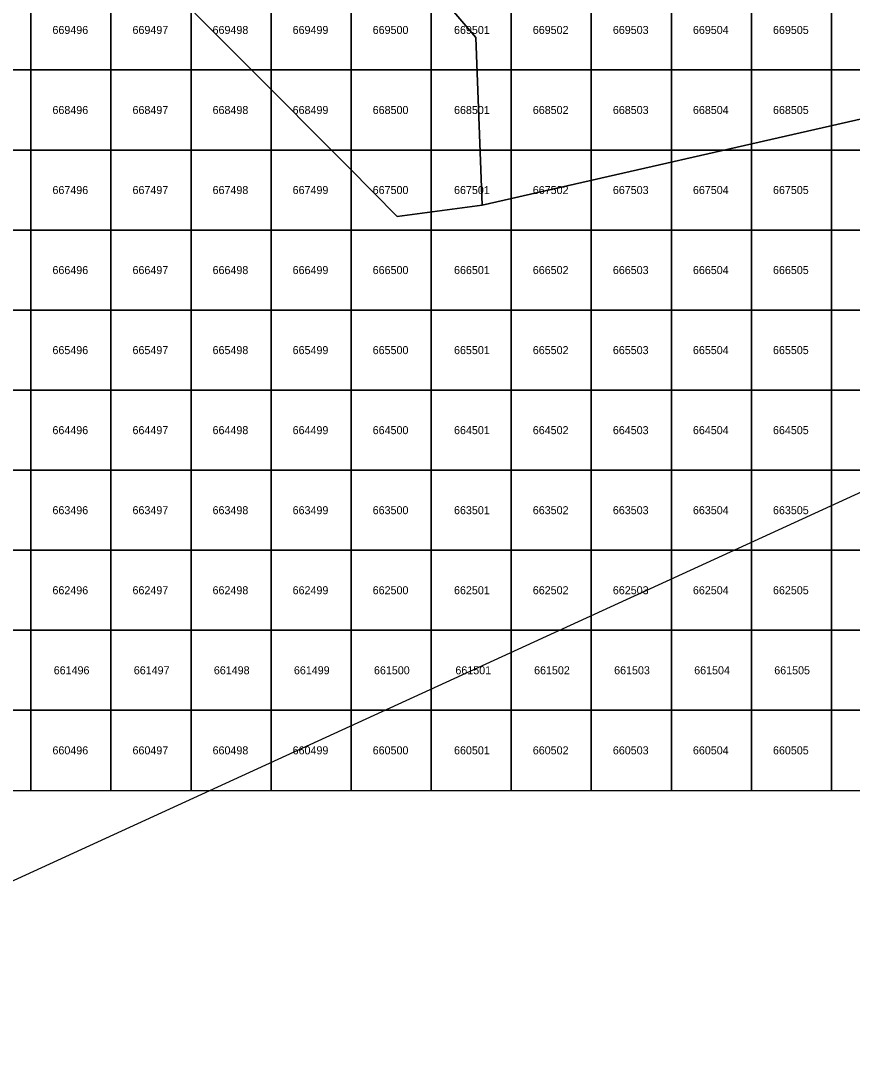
# Model space of a CAD drawing. Extents: x 25485000 to 25520000, y 6656775 to 6690000.
# Drawn here: x 25495870 to 25506262, y 6656775 to 6669617 of the extents above; entities that cross this region are included whole.
import ezdxf

# ---------------------------------------------------------------- set-up
doc = ezdxf.new("R2010")
doc.units = 0
doc.layers.add('Level 63', color=7, linetype='Continuous')

msp = doc.modelspace()

# ---------------------------------------------------------------- linework, layer by layer
at = {"layer": 'Level 63'}
for points in [[(25497357, 6670410), (25497407, 6670360), (25499970, 6667780), (25500576, 6667171), (25501638, 6667311), (25501556, 6669405), (25501232, 6669785), (25501233, 6670418), (25501234, 6671696), (25501017, 6671717), (25500288, 6671786), (25497878, 6670961), (25497622, 6671122), (25497572, 6671153), (25497412, 6670926)], [(25495000, 6669000), (25496000, 6669000), (25496000, 6670000), (25495000, 6670000)], [(25496000, 6669000), (25497000, 6669000), (25497000, 6670000), (25496000, 6670000)], [(25497000, 6669000), (25498000, 6669000), (25498000, 6670000), (25497000, 6670000)], [(25498000, 6669000), (25499000, 6669000), (25499000, 6670000), (25498000, 6670000)], [(25499000, 6669000), (25500000, 6669000), (25500000, 6670000), (25499000, 6670000)], [(25500000, 6669000), (25501000, 6669000), (25501000, 6670000), (25500000, 6670000)], [(25501000, 6669000), (25502000, 6669000), (25502000, 6670000), (25501000, 6670000)], [(25502000, 6669000), (25503000, 6669000), (25503000, 6670000), (25502000, 6670000)], [(25503000, 6669000), (25504000, 6669000), (25504000, 6670000), (25503000, 6670000)], [(25504000, 6669000), (25505000, 6669000), (25505000, 6670000), (25504000, 6670000)], [(25505000, 6669000), (25506000, 6669000), (25506000, 6670000), (25505000, 6670000)], [(25506000, 6669000), (25507000, 6669000), (25507000, 6670000), (25506000, 6670000)], [(25495000, 6668000), (25496000, 6668000), (25496000, 6669000), (25495000, 6669000)], [(25496000, 6668000), (25497000, 6668000), (25497000, 6669000), (25496000, 6669000)], [(25497000, 6668000), (25498000, 6668000), (25498000, 6669000), (25497000, 6669000)], [(25498000, 6668000), (25499000, 6668000), (25499000, 6669000), (25498000, 6669000)], [(25499000, 6668000), (25500000, 6668000), (25500000, 6669000), (25499000, 6669000)], [(25500000, 6668000), (25501000, 6668000), (25501000, 6669000), (25500000, 6669000)], [(25501000, 6668000), (25502000, 6668000), (25502000, 6669000), (25501000, 6669000)], [(25502000, 6668000), (25503000, 6668000), (25503000, 6669000), (25502000, 6669000)], [(25503000, 6668000), (25504000, 6668000), (25504000, 6669000), (25503000, 6669000)], [(25504000, 6668000), (25505000, 6668000), (25505000, 6669000), (25504000, 6669000)], [(25505000, 6668000), (25506000, 6668000), (25506000, 6669000), (25505000, 6669000)], [(25506000, 6668000), (25507000, 6668000), (25507000, 6669000), (25506000, 6669000)], [(25495000, 6667000), (25496000, 6667000), (25496000, 6668000), (25495000, 6668000)], [(25496000, 6667000), (25497000, 6667000), (25497000, 6668000), (25496000, 6668000)], [(25497000, 6667000), (25498000, 6667000), (25498000, 6668000), (25497000, 6668000)], [(25498000, 6667000), (25499000, 6667000), (25499000, 6668000), (25498000, 6668000)], [(25499000, 6667000), (25500000, 6667000), (25500000, 6668000), (25499000, 6668000)], [(25500000, 6667000), (25501000, 6667000), (25501000, 6668000), (25500000, 6668000)], [(25501000, 6667000), (25502000, 6667000), (25502000, 6668000), (25501000, 6668000)], [(25502000, 6667000), (25503000, 6667000), (25503000, 6668000), (25502000, 6668000)], [(25503000, 6667000), (25504000, 6667000), (25504000, 6668000), (25503000, 6668000)], [(25504000, 6667000), (25505000, 6667000), (25505000, 6668000), (25504000, 6668000)], [(25505000, 6667000), (25506000, 6667000), (25506000, 6668000), (25505000, 6668000)], [(25506000, 6667000), (25507000, 6667000), (25507000, 6668000), (25506000, 6668000)], [(25495000, 6666000), (25496000, 6666000), (25496000, 6667000), (25495000, 6667000)], [(25496000, 6666000), (25497000, 6666000), (25497000, 6667000), (25496000, 6667000)], [(25497000, 6666000), (25498000, 6666000), (25498000, 6667000), (25497000, 6667000)], [(25498000, 6666000), (25499000, 6666000), (25499000, 6667000), (25498000, 6667000)], [(25499000, 6666000), (25500000, 6666000), (25500000, 6667000), (25499000, 6667000)], [(25500000, 6666000), (25501000, 6666000), (25501000, 6667000), (25500000, 6667000)], [(25501000, 6666000), (25502000, 6666000), (25502000, 6667000), (25501000, 6667000)], [(25502000, 6666000), (25503000, 6666000), (25503000, 6667000), (25502000, 6667000)], [(25503000, 6666000), (25504000, 6666000), (25504000, 6667000), (25503000, 6667000)], [(25504000, 6666000), (25505000, 6666000), (25505000, 6667000), (25504000, 6667000)], [(25505000, 6666000), (25506000, 6666000), (25506000, 6667000), (25505000, 6667000)], [(25506000, 6666000), (25507000, 6666000), (25507000, 6667000), (25506000, 6667000)], [(25495000, 6665000), (25496000, 6665000), (25496000, 6666000), (25495000, 6666000)], [(25496000, 6665000), (25497000, 6665000), (25497000, 6666000), (25496000, 6666000)], [(25497000, 6665000), (25498000, 6665000), (25498000, 6666000), (25497000, 6666000)], [(25498000, 6665000), (25499000, 6665000), (25499000, 6666000), (25498000, 6666000)], [(25499000, 6665000), (25500000, 6665000), (25500000, 6666000), (25499000, 6666000)], [(25500000, 6665000), (25501000, 6665000), (25501000, 6666000), (25500000, 6666000)], [(25501000, 6665000), (25502000, 6665000), (25502000, 6666000), (25501000, 6666000)], [(25502000, 6665000), (25503000, 6665000), (25503000, 6666000), (25502000, 6666000)], [(25503000, 6665000), (25504000, 6665000), (25504000, 6666000), (25503000, 6666000)], [(25504000, 6665000), (25505000, 6665000), (25505000, 6666000), (25504000, 6666000)], [(25505000, 6665000), (25506000, 6665000), (25506000, 6666000), (25505000, 6666000)], [(25506000, 6665000), (25507000, 6665000), (25507000, 6666000), (25506000, 6666000)], [(25495000, 6664000), (25496000, 6664000), (25496000, 6665000), (25495000, 6665000)], [(25496000, 6664000), (25497000, 6664000), (25497000, 6665000), (25496000, 6665000)], [(25497000, 6664000), (25498000, 6664000), (25498000, 6665000), (25497000, 6665000)], [(25498000, 6664000), (25499000, 6664000), (25499000, 6665000), (25498000, 6665000)], [(25499000, 6664000), (25500000, 6664000), (25500000, 6665000), (25499000, 6665000)], [(25500000, 6664000), (25501000, 6664000), (25501000, 6665000), (25500000, 6665000)], [(25501000, 6664000), (25502000, 6664000), (25502000, 6665000), (25501000, 6665000)], [(25502000, 6664000), (25503000, 6664000), (25503000, 6665000), (25502000, 6665000)], [(25503000, 6664000), (25504000, 6664000), (25504000, 6665000), (25503000, 6665000)], [(25504000, 6664000), (25505000, 6664000), (25505000, 6665000), (25504000, 6665000)], [(25505000, 6664000), (25506000, 6664000), (25506000, 6665000), (25505000, 6665000)], [(25506000, 6664000), (25507000, 6664000), (25507000, 6665000), (25506000, 6665000)], [(25495000, 6663000), (25496000, 6663000), (25496000, 6664000), (25495000, 6664000)], [(25496000, 6663000), (25497000, 6663000), (25497000, 6664000), (25496000, 6664000)], [(25497000, 6663000), (25498000, 6663000), (25498000, 6664000), (25497000, 6664000)], [(25498000, 6663000), (25499000, 6663000), (25499000, 6664000), (25498000, 6664000)], [(25499000, 6663000), (25500000, 6663000), (25500000, 6664000), (25499000, 6664000)], [(25500000, 6663000), (25501000, 6663000), (25501000, 6664000), (25500000, 6664000)], [(25501000, 6663000), (25502000, 6663000), (25502000, 6664000), (25501000, 6664000)], [(25502000, 6663000), (25503000, 6663000), (25503000, 6664000), (25502000, 6664000)], [(25503000, 6663000), (25504000, 6663000), (25504000, 6664000), (25503000, 6664000)], [(25504000, 6663000), (25505000, 6663000), (25505000, 6664000), (25504000, 6664000)], [(25505000, 6663000), (25506000, 6663000), (25506000, 6664000), (25505000, 6664000)], [(25506000, 6663000), (25507000, 6663000), (25507000, 6664000), (25506000, 6664000)], [(25495000, 6662000), (25496000, 6662000), (25496000, 6663000), (25495000, 6663000)], [(25496000, 6662000), (25497000, 6662000), (25497000, 6663000), (25496000, 6663000)], [(25497000, 6662000), (25498000, 6662000), (25498000, 6663000), (25497000, 6663000)], [(25498000, 6662000), (25499000, 6662000), (25499000, 6663000), (25498000, 6663000)], [(25499000, 6662000), (25500000, 6662000), (25500000, 6663000), (25499000, 6663000)], [(25500000, 6662000), (25501000, 6662000), (25501000, 6663000), (25500000, 6663000)], [(25501000, 6662000), (25502000, 6662000), (25502000, 6663000), (25501000, 6663000)], [(25502000, 6662000), (25503000, 6662000), (25503000, 6663000), (25502000, 6663000)], [(25503000, 6662000), (25504000, 6662000), (25504000, 6663000), (25503000, 6663000)], [(25504000, 6662000), (25505000, 6662000), (25505000, 6663000), (25504000, 6663000)], [(25505000, 6662000), (25506000, 6662000), (25506000, 6663000), (25505000, 6663000)], [(25506000, 6662000), (25507000, 6662000), (25507000, 6663000), (25506000, 6663000)], [(25495000, 6661000), (25496000, 6661000), (25496000, 6662000), (25495000, 6662000)], [(25496000, 6661000), (25497000, 6661000), (25497000, 6662000), (25496000, 6662000)], [(25497000, 6661000), (25498000, 6661000), (25498000, 6662000), (25497000, 6662000)], [(25498000, 6661000), (25499000, 6661000), (25499000, 6662000), (25498000, 6662000)], [(25499000, 6661000), (25500000, 6661000), (25500000, 6662000), (25499000, 6662000)], [(25500000, 6661000), (25501000, 6661000), (25501000, 6662000), (25500000, 6662000)], [(25501000, 6661000), (25502000, 6661000), (25502000, 6662000), (25501000, 6662000)], [(25502000, 6661000), (25503000, 6661000), (25503000, 6662000), (25502000, 6662000)], [(25503000, 6661000), (25504000, 6661000), (25504000, 6662000), (25503000, 6662000)], [(25504000, 6661000), (25505000, 6661000), (25505000, 6662000), (25504000, 6662000)], [(25505000, 6661000), (25506000, 6661000), (25506000, 6662000), (25505000, 6662000)], [(25506000, 6661000), (25507000, 6661000), (25507000, 6662000), (25506000, 6662000)], [(25495000, 6660000), (25496000, 6660000), (25496000, 6661000), (25495000, 6661000)], [(25496000, 6660000), (25497000, 6660000), (25497000, 6661000), (25496000, 6661000)], [(25497000, 6660000), (25498000, 6660000), (25498000, 6661000), (25497000, 6661000)], [(25498000, 6660000), (25499000, 6660000), (25499000, 6661000), (25498000, 6661000)], [(25499000, 6660000), (25500000, 6660000), (25500000, 6661000), (25499000, 6661000)], [(25500000, 6660000), (25501000, 6660000), (25501000, 6661000), (25500000, 6661000)], [(25501000, 6660000), (25502000, 6660000), (25502000, 6661000), (25501000, 6661000)], [(25502000, 6660000), (25503000, 6660000), (25503000, 6661000), (25502000, 6661000)], [(25503000, 6660000), (25504000, 6660000), (25504000, 6661000), (25503000, 6661000)], [(25504000, 6660000), (25505000, 6660000), (25505000, 6661000), (25504000, 6661000)], [(25505000, 6660000), (25506000, 6660000), (25506000, 6661000), (25505000, 6661000)], [(25506000, 6660000), (25507000, 6660000), (25507000, 6661000), (25506000, 6661000)]]:
    msp.add_lwpolyline(points, close=True, dxfattribs=at)
for points in [[(25506580, 6668434), (25501638, 6667311), (25500576, 6667171), (25499970, 6667780), (25497407, 6670360), (25497357, 6670410), (25496638, 6670410), (25496588, 6670411), (25496587, 6669968), (25495369, 6669969), (25494290, 6669969), (25494289, 6669645), (25492634, 6669823), (25491001, 6669998), (25490933, 6669294), (25490867, 6668614), (25487917, 6665230), (25489109, 6662564), (25491530, 6657153), (25491699, 6656775), (25493980, 6658048), (25507391, 6664195)], [(25501232, 6669785), (25501556, 6669405), (25501638, 6667311), (25506580, 6668434)]]:
    msp.add_lwpolyline(points, dxfattribs=at)

# ---------------------------------------------------------------- texts
for s, p in [('669496', (25496269, 6669450)), ('669497', (25497269, 6669450)), ('669498', (25498269, 6669450)), ('669499', (25499269, 6669450)), ('669500', (25500269, 6669450)), ('669501', (25501285, 6669450)), ('669502', (25502269, 6669450)), ('669503', (25503269, 6669450)), ('669504', (25504269, 6669450)), ('669505', (25505269, 6669450)), ('668496', (25496269, 6668450)), ('668497', (25497269, 6668450)), ('668498', (25498269, 6668450)), ('668499', (25499269, 6668450)), ('668500', (25500269, 6668450)), ('668501', (25501285, 6668450)), ('668502', (25502269, 6668450)), ('668503', (25503269, 6668450)), ('668504', (25504269, 6668450)), ('668505', (25505269, 6668450)), ('667496', (25496269, 6667450)), ('667497', (25497269, 6667450)), ('667498', (25498269, 6667450)), ('667499', (25499269, 6667450)), ('667500', (25500269, 6667450)), ('667501', (25501285, 6667450)), ('667502', (25502269, 6667450)), ('667503', (25503269, 6667450)), ('667504', (25504269, 6667450)), ('667505', (25505269, 6667450)), ('666496', (25496269, 6666450)), ('666497', (25497269, 6666450)), ('666498', (25498269, 6666450)), ('666499', (25499269, 6666450)), ('666500', (25500269, 6666450)), ('666501', (25501285, 6666450)), ('666502', (25502269, 6666450)), ('666503', (25503269, 6666450)), ('666504', (25504269, 6666450)), ('666505', (25505269, 6666450)), ('665496', (25496269, 6665450)), ('665497', (25497269, 6665450)), ('665498', (25498269, 6665450)), ('665499', (25499269, 6665450)), ('665500', (25500269, 6665450)), ('665501', (25501285, 6665450)), ('665502', (25502269, 6665450)), ('665503', (25503269, 6665450)), ('665504', (25504269, 6665450)), ('665505', (25505269, 6665450)), ('664496', (25496269, 6664450)), ('664497', (25497269, 6664450)), ('664498', (25498269, 6664450)), ('664499', (25499269, 6664450)), ('664500', (25500269, 6664450)), ('664501', (25501285, 6664450)), ('664502', (25502269, 6664450)), ('664503', (25503269, 6664450)), ('664504', (25504269, 6664450)), ('664505', (25505269, 6664450)), ('663496', (25496269, 6663450)), ('663497', (25497269, 6663450)), ('663498', (25498269, 6663450)), ('663499', (25499269, 6663450)), ('663500', (25500269, 6663450)), ('663501', (25501285, 6663450)), ('663502', (25502269, 6663450)), ('663503', (25503269, 6663450)), ('663504', (25504269, 6663450)), ('663505', (25505269, 6663450)), ('662496', (25496269, 6662450)), ('662497', (25497269, 6662450)), ('662498', (25498269, 6662450)), ('662499', (25499269, 6662450)), ('662500', (25500269, 6662450)), ('662501', (25501285, 6662450)), ('662502', (25502269, 6662450)), ('662503', (25503269, 6662450)), ('662504', (25504269, 6662450)), ('662505', (25505269, 6662450)), ('661496', (25496285, 6661450)), ('661497', (25497285, 6661450)), ('661498', (25498285, 6661450)), ('661499', (25499285, 6661450)), ('661500', (25500285, 6661450)), ('661501', (25501302, 6661450)), ('661502', (25502285, 6661450)), ('661503', (25503285, 6661450)), ('661504', (25504285, 6661450)), ('661505', (25505285, 6661450)), ('660496', (25496269, 6660450)), ('660497', (25497269, 6660450)), ('660498', (25498269, 6660450)), ('660499', (25499269, 6660450)), ('660500', (25500269, 6660450)), ('660501', (25501285, 6660450)), ('660502', (25502269, 6660450)), ('660503', (25503269, 6660450)), ('660504', (25504269, 6660450)), ('660505', (25505269, 6660450))]:
    msp.add_text(s, height=100, dxfattribs=at).set_placement(p)

doc.saveas('drawing.dxf')
